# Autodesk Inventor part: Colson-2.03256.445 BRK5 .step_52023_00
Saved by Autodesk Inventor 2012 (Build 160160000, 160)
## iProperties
Created: 2010-10
Part Number: Colson-2.03256.445 BRK5 .step_52023_00
Document SubType Name: Modeling
Designer: Administrator
Density: 1 g/cm^3
Mass: 5.39508 g
Surface Area: 54.6086 cm^2
Volume: 5.39508 cm^3
Material: Default
Author: Administrator
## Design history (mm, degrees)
feature "Base1"
body "Solid1"
